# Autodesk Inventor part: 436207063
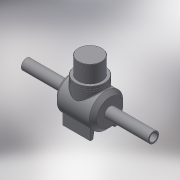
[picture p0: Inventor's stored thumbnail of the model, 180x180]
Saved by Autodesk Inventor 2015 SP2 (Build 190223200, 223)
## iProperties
Created: 2017-08
Part Number: 436207063
Material: Generic
Description: PLASSON PE BALL VALVE 63
Document SubType Name: Modeling
Designer: Кирилл
Density: 1 g/cm^3
Appearance: Default
Author: Кирилл
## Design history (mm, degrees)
derived "436207.ipt"
feature "Solid1::436207.ipt"
feature "Solid2::436207.ipt"
tag "TaggingFeature1"
body "Solid1"
other parameters: "d0" = 414, "d1" = 63, "d5" = 47.25, "d6" = 12.42, "d10" = 85, "d11" = 68, "d12" = 0.85, "d13" = 4, "d14" = 4, "d16" = 100 deg, "d17" = 48, "d18" = 9.6, "d20" = 87, "d21" = 0, "d22" = 0.85, "d26" = 6, "d28" = 0, "d29" = 1.7, "d_" = 63, "s_" = 6, "L_" = 414, "B_" = 87, "E_1" = 85
